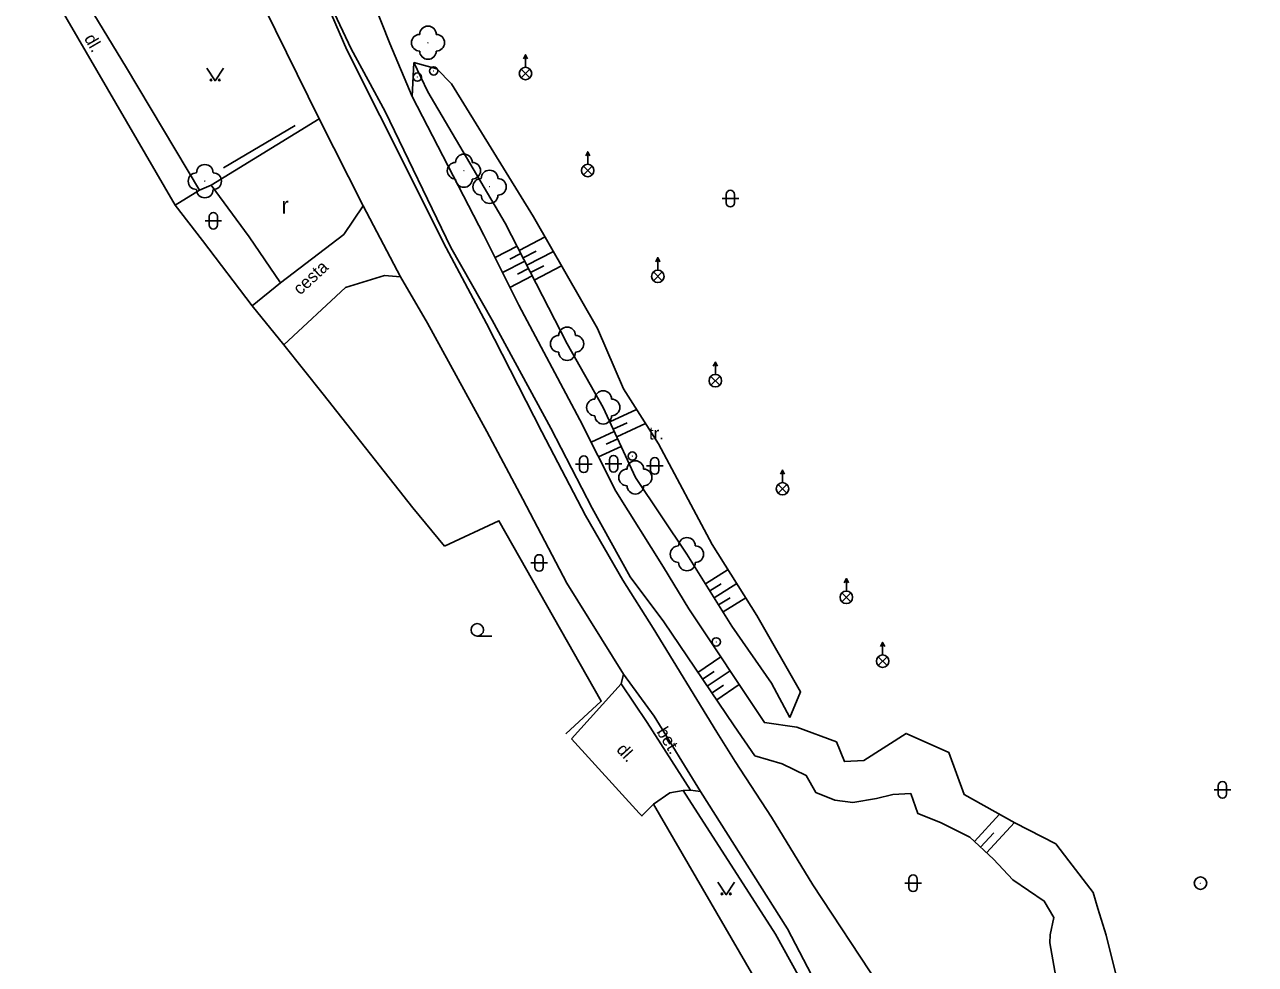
# Model space of a CAD drawing. Extents: x -582188 to -561562, y -1187250 to -1183500.
# Drawn here: x -578267.1 to -578193.2, y -1186086.2 to -1186029.8 of the extents above; entities that cross this region are included whole.
import ezdxf

# ---------------------------------------------------------------- set-up
doc = ezdxf.new("R2010")
doc.units = 0
for name, color, linetype in [('BUDOVY_MĚŘ', 7, 'Continuous'), ('MAP_ZN_BP', 7, 'Continuous'), ('POMOC_POPIS', 7, 'Continuous'), ('ROZHRANÍ_PLOCH', 7, 'Continuous'), ('VÝŠKOPIS', 7, 'Continuous'), ('ZELEŇ', 7, 'Continuous'), ('ZN_BP', 7, 'Continuous'), ('ZN_DOPLŇKOVÉ', 7, 'Continuous'), ('ZN_KULTUR', 7, 'Continuous')]:
    doc.layers.add(name, color=color, linetype=linetype)

msp = doc.modelspace()

# ---------------------------------------------------------------- linework, layer by layer
at = {"layer": 'BUDOVY_MĚŘ'}
for p, q in [((-578256.43, -1186042.75), (-578258.07, -1186040.62)), ((-578230.19, -1186077.16), (-578234.26, -1186072.68))]:
    msp.add_line(p, q, dxfattribs=at)
for points in [[(-578258.07, -1186040.62), (-578265.71, -1186027.49), (-578267.12, -1186025.25)], [(-578249.17, -1186051.97), (-578251.54, -1186049.02)]]:
    msp.add_lwpolyline(points, dxfattribs=at)
at = {"layer": 'MAP_ZN_BP'}
for radius in [0.375, 0.0005]:
    msp.add_circle((-578196.46, -1186081.36), radius, dxfattribs=at)
at = {"layer": 'ROZHRANÍ_PLOCH'}
msp.add_line((-578251.75, -1186045.28), (-578253.44, -1186046.68), dxfattribs=at)
for points in [[(-578219.75, -1186081.45), (-578222.24, -1186077.4), (-578224.42, -1186074.05), (-578225.53, -1186072.28), (-578229.35, -1186066.03), (-578231.18, -1186063.15), (-578233.42, -1186059.26), (-578236.04, -1186054.25), (-578239.37, -1186047.73), (-578241.79, -1186043.18), (-578245.77, -1186035.23), (-578247.75, -1186031.28), (-578251.05, -1186023.69), (-578253.76, -1186017.08), (-578256.85, -1186008.5), (-578257.98, -1186005.5)], [(-578234.26, -1186072.68), (-578231.28, -1186069.39), (-578231.13, -1186068.8), (-578234.53, -1186063.34), (-578237.18, -1186058.28), (-578239.34, -1186054.23), (-578242.91, -1186047.72), (-578244.54, -1186044.93), (-578246.77, -1186040.67), (-578249.42, -1186035.43), (-578252.71, -1186028.77), (-578254.42, -1186025.06), (-578254.87, -1186024.59), (-578255.45, -1186024.14), (-578257.13, -1186023.85), (-578257.51, -1186023.81), (-578258.52, -1186023.89), (-578259.53, -1186024.12), (-578260.54, -1186024.49), (-578261.18, -1186024.85), (-578263.33, -1186026.15), (-578264.37, -1186026.83), (-578261, -1186032.38)], [(-578258.07, -1186040.62), (-578256.61, -1186039.73), (-578261, -1186032.38)], [(-578251.54, -1186049.02), (-578247.83, -1186045.57), (-578245.5, -1186044.85), (-578244.54, -1186044.93)], [(-578226.5, -1186075.85), (-578229.28, -1186071.33), (-578231.13, -1186068.8)], [(-578227.11, -1186075.77), (-578229.71, -1186071.7), (-578231.28, -1186069.39)], [(-578216.48, -1186097.76), (-578216.4, -1186097.41), (-578216.48, -1186095.19), (-578217.13, -1186092.49), (-578218.12, -1186090.11), (-578219.59, -1186087.32), (-578221.27, -1186084.09), (-578226.5, -1186075.85), (-578227.11, -1186075.77), (-578227.54, -1186075.79), (-578228.35, -1186075.93), (-578229.33, -1186076.61)], [(-578225.47, -1186114.85), (-578217.9, -1186107.52), (-578215.38, -1186104.13), (-578213.87, -1186101.45), (-578213.11, -1186099.12), (-578212.78, -1186096.87), (-578213.36, -1186093.58), (-578214.32, -1186090.08), (-578215.76, -1186087.51), (-578219.75, -1186081.45)]]:
    msp.add_lwpolyline(points, dxfattribs=at)
at = {"layer": 'VÝŠKOPIS'}
for p, q in [((-578237.53, -1186043.09), (-578238.85, -1186043.77)), ((-578237.4, -1186043.34), (-578235.84, -1186042.53)), ((-578237.07, -1186043.98), (-578238.41, -1186044.66)), ((-578237.3, -1186043.53), (-578237.97, -1186043.87)), ((-578237.17, -1186043.78), (-578236.38, -1186043.38)), ((-578236.95, -1186044.23), (-578235.34, -1186043.4)), ((-578236.85, -1186044.42), (-578237.51, -1186044.77)), ((-578236.72, -1186044.67), (-578235.91, -1186044.26)), ((-578236.49, -1186045.12), (-578234.85, -1186044.27)), ((-578236.62, -1186044.87), (-578237.96, -1186045.56)), ((-578231.96, -1186053.63), (-578230.35, -1186052.89)), ((-578231.69, -1186054.22), (-578233.08, -1186054.86)), ((-578231.75, -1186054.08), (-578230.91, -1186053.7)), ((-578231.54, -1186054.54), (-578229.81, -1186053.74)), ((-578231.48, -1186054.67), (-578232.17, -1186054.99)), ((-578231.27, -1186055.13), (-578232.63, -1186055.75)), ((-578226.21, -1186063.37), (-578224.85, -1186062.52)), ((-578225.95, -1186063.79), (-578225.26, -1186063.37)), ((-578225.68, -1186064.22), (-578224.32, -1186063.36)), ((-578225.42, -1186064.64), (-578224.73, -1186064.21)), ((-578225.15, -1186065.06), (-578223.78, -1186064.21)), ((-578226.66, -1186068.69), (-578225.28, -1186067.76)), ((-578226.38, -1186069.1), (-578225.69, -1186068.64)), ((-578226.1, -1186069.52), (-578224.73, -1186068.59)), ((-578225.81, -1186069.93), (-578225.13, -1186069.47)), ((-578225.53, -1186070.35), (-578224.18, -1186069.43)), ((-578210.04, -1186078.86), (-578208.53, -1186077.22)), ((-578209.31, -1186079.54), (-578207.63, -1186077.72)), ((-578209.67, -1186079.2), (-578208.88, -1186078.33))]:
    msp.add_line(p, q, dxfattribs=at)
for points in [[(-578202.62, -1186082.87), (-578202.91, -1186081.92), (-578204.38, -1186080.01), (-578205.15, -1186079), (-578207.62, -1186077.73), (-578210.65, -1186076.03), (-578211.59, -1186073.5), (-578214.15, -1186072.36), (-578216.68, -1186073.99), (-578217.86, -1186074.05), (-578218.34, -1186072.86), (-578220.72, -1186071.98), (-578222.66, -1186071.71), (-578227.2, -1186064.87), (-578228.72, -1186062.37), (-578231.6, -1186057.81), (-578233.76, -1186053.51), (-578237.42, -1186046.63), (-578239.53, -1186042.42), (-578243.84, -1186034.09), (-578245.17, -1186030.9), (-578248.92, -1186021.45), (-578249.33, -1186019.24), (-578250.64, -1186018.18)], [(-578205.51, -1186084.95), (-578205.5, -1186084.45), (-578205.28, -1186083.41), (-578205.85, -1186082.43), (-578207.74, -1186081.15), (-578208.9, -1186079.91), (-578210.32, -1186078.6), (-578212.08, -1186077.72), (-578213.45, -1186077.18), (-578213.87, -1186075.97), (-578214.94, -1186076.02), (-578215.93, -1186076.26), (-578217.36, -1186076.51), (-578218.43, -1186076.36), (-578219.58, -1186075.9), (-578220.15, -1186074.89), (-578221.59, -1186074.18), (-578223.23, -1186073.7), (-578224.48, -1186071.9), (-578228.71, -1186065.66), (-578230.73, -1186062.96), (-578233.01, -1186058.82), (-578235.49, -1186054.01), (-578239.02, -1186047.54), (-578241.5, -1186043.17), (-578245.45, -1186035), (-578247.49, -1186031.23), (-578251.05, -1186023.69)], [(-578243.84, -1186034.09), (-578243.74, -1186032.05)], [(-578221.14, -1186071.41), (-578222.23, -1186069.34), (-578224.62, -1186065.92), (-578227.32, -1186061.59), (-578230.42, -1186056.98), (-578232.35, -1186052.77), (-578234.52, -1186048.95), (-578238.24, -1186041.71), (-578242.88, -1186033.81), (-578243.74, -1186032.05)], [(-578221.14, -1186071.41), (-578220.49, -1186069.87), (-578223.11, -1186065.27), (-578225.81, -1186061), (-578229.02, -1186054.97), (-578231.14, -1186051.65), (-578232.7, -1186048.04), (-578236.53, -1186041.32), (-578241.47, -1186033.34), (-578242.35, -1186032.44), (-578243.74, -1186032.05)], [(-578193.16, -1186096.5), (-578194.64, -1186092.79), (-578195.32, -1186091.59), (-578198.18, -1186089.13), (-578201.52, -1186086.91), (-578202.13, -1186084.47), (-578202.62, -1186082.87)], [(-578193.16, -1186096.5), (-578195.8, -1186093.08), (-578198.12, -1186091.38), (-578202.97, -1186089.67), (-578204.88, -1186088.57), (-578205.51, -1186084.95)]]:
    msp.add_lwpolyline(points, dxfattribs=at)
at = {"layer": 'ZELEŇ'}
msp.add_line((-578255.17, -1186038.38), (-578250.86, -1186035.83), dxfattribs=at)
for points in [[(-578246.77, -1186040.67), (-578247.94, -1186042.38), (-578251.75, -1186045.28), (-578253.63, -1186042.53), (-578255.91, -1186039.43), (-578249.42, -1186035.43)], [(-578255.91, -1186039.43), (-578256.61, -1186039.73)], [(-578216.9, -1186097.97), (-578216.84, -1186095.77), (-578217.61, -1186092.95), (-578218.55, -1186090.48), (-578220.12, -1186087.82), (-578221.99, -1186084.41), (-578227.54, -1186075.79)]]:
    msp.add_lwpolyline(points, dxfattribs=at)
for centre in [(-578242.88, -1186030.86), (-578240.72, -1186038.55), (-578256.29, -1186039.18), (-578239.18, -1186039.52), (-578234.52, -1186048.95), (-578232.35, -1186052.77), (-578230.42, -1186056.98), (-578227.32, -1186061.59)]:
    msp.add_circle(centre, 0.0005, dxfattribs=at)
for centre, start, end in [((-578242.88, -1186030.36), 0, 179.99999), ((-578243.38, -1186030.86), 89.99999, 269.99999), ((-578242.38, -1186030.86), 270, 89.99999), ((-578242.88, -1186031.36), 179.99999, 359.99999), ((-578241.22, -1186038.55), 89.99999, 269.99999), ((-578240.72, -1186038.05), 0, 179.99999), ((-578240.22, -1186038.55), 270, 89.99999), ((-578256.79, -1186039.18), 89.99999, 269.99999), ((-578256.29, -1186038.68), 0, 179.99999), ((-578255.79, -1186039.18), 270, 89.99999), ((-578239.18, -1186039.02), 0, 179.99999), ((-578240.72, -1186039.05), 179.99999, 359.99999), ((-578239.68, -1186039.52), 89.99999, 269.99999), ((-578238.68, -1186039.52), 270, 89.99999), ((-578256.29, -1186039.68), 179.99999, 359.99999), ((-578239.18, -1186040.02), 179.99999, 359.99999), ((-578234.52, -1186048.45), 0, 179.99999), ((-578235.02, -1186048.95), 89.99999, 269.99999), ((-578234.02, -1186048.95), 270, 89.99999), ((-578234.52, -1186049.45), 179.99999, 359.99999), ((-578232.35, -1186052.27), 0, 179.99999), ((-578232.85, -1186052.77), 89.99999, 269.99999), ((-578231.85, -1186052.77), 270, 89.99999), ((-578232.35, -1186053.27), 179.99999, 359.99999), ((-578230.92, -1186056.98), 89.99999, 269.99999), ((-578230.42, -1186056.48), 0, 179.99999), ((-578229.92, -1186056.98), 270, 89.99999), ((-578230.42, -1186057.48), 179.99999, 359.99999), ((-578227.32, -1186061.09), 0, 179.99999), ((-578227.82, -1186061.59), 89.99999, 269.99999), ((-578226.82, -1186061.59), 270, 89.99999), ((-578227.32, -1186062.09), 179.99999, 359.99999)]:
    msp.add_arc(centre, 0.5, start, end, dxfattribs=at)
at = {"layer": 'ZN_BP'}
for p, q in [((-578237.02, -1186032.335), (-578237.02, -1186031.585)), ((-578237.285, -1186032.974), (-578236.756, -1186032.446)), ((-578236.756, -1186032.978), (-578237.285, -1186032.446)), ((-578233.28, -1186038.165), (-578233.28, -1186037.415)), ((-578233.545, -1186038.804), (-578233.016, -1186038.276)), ((-578233.016, -1186038.808), (-578233.545, -1186038.276)), ((-578229.07, -1186044.525), (-578229.07, -1186043.775)), ((-578229.335, -1186045.164), (-578228.806, -1186044.636)), ((-578228.806, -1186045.168), (-578229.335, -1186044.636)), ((-578225.61, -1186050.795), (-578225.61, -1186050.045)), ((-578225.875, -1186051.434), (-578225.346, -1186050.906)), ((-578225.346, -1186051.438), (-578225.875, -1186050.906)), ((-578221.58, -1186057.285), (-578221.58, -1186056.535)), ((-578221.845, -1186057.924), (-578221.316, -1186057.396)), ((-578221.316, -1186057.928), (-578221.845, -1186057.396)), ((-578217.74, -1186063.805), (-578217.74, -1186063.055)), ((-578218.005, -1186064.444), (-578217.476, -1186063.916)), ((-578217.476, -1186064.448), (-578218.005, -1186063.916)), ((-578215.56, -1186067.645), (-578215.56, -1186066.895)), ((-578215.825, -1186068.284), (-578215.296, -1186067.756)), ((-578215.296, -1186068.288), (-578215.825, -1186067.756))]:
    msp.add_line(p, q, dxfattribs=at)
for points in [[(-578237.145, -1186031.835), (-578237.02, -1186031.585), (-578236.895, -1186031.835)], [(-578233.405, -1186037.665), (-578233.28, -1186037.415), (-578233.155, -1186037.665)], [(-578229.195, -1186044.025), (-578229.07, -1186043.775), (-578228.945, -1186044.025)], [(-578225.735, -1186050.295), (-578225.61, -1186050.045), (-578225.485, -1186050.295)], [(-578221.705, -1186056.785), (-578221.58, -1186056.535), (-578221.455, -1186056.785)], [(-578217.865, -1186063.305), (-578217.74, -1186063.055), (-578217.615, -1186063.305)], [(-578215.685, -1186067.145), (-578215.56, -1186066.895), (-578215.435, -1186067.145)]]:
    msp.add_lwpolyline(points, dxfattribs=at)
for centre, radius in [((-578243.52, -1186032.93), 0.25), ((-578242.54, -1186032.56), 0.25), ((-578242.54, -1186032.56), 0.0005), ((-578237.02, -1186032.71), 0.375), ((-578243.52, -1186032.93), 0.0005), ((-578233.28, -1186038.54), 0.375), ((-578229.07, -1186044.9), 0.375), ((-578225.61, -1186051.17), 0.375), ((-578221.58, -1186057.66), 0.375), ((-578217.74, -1186064.18), 0.375), ((-578225.56, -1186066.86), 0.25), ((-578225.56, -1186066.86), 0.0005), ((-578215.56, -1186068.02), 0.375)]:
    msp.add_circle(centre, radius, dxfattribs=at)
at = {"layer": 'ZN_DOPLŇKOVÉ'}
for p, q in [((-578253.44, -1186046.68), (-578256.43, -1186042.75)), ((-578251.54, -1186049.02), (-578253.44, -1186046.68))]:
    msp.add_line(p, q, dxfattribs=at)
for points in [[(-578243.79, -1186058.81), (-578249.17, -1186051.97)], [(-578241.89, -1186061.11), (-578243.79, -1186058.81)], [(-578234.6, -1186072.38), (-578232.47, -1186070.43), (-578238.62, -1186059.58), (-578241.89, -1186061.11)], [(-578216.9, -1186097.97), (-578229.33, -1186076.61), (-578230.02, -1186077.32), (-578230.19, -1186077.16)]]:
    msp.add_lwpolyline(points, dxfattribs=at)
for radius in [0.25, 0.0005]:
    msp.add_circle((-578230.601, -1186055.7), radius, dxfattribs=at)
at = {"layer": 'ZN_KULTUR'}
for p, q in [((-578225.21, -1186040.23), (-578224.21, -1186040.23)), ((-578224.96, -1186040.48), (-578224.96, -1186039.98)), ((-578224.46, -1186040.48), (-578224.46, -1186039.98)), ((-578256.28, -1186041.56), (-578255.28, -1186041.56)), ((-578256.03, -1186041.81), (-578256.03, -1186041.31)), ((-578255.53, -1186041.81), (-578255.53, -1186041.31)), ((-578234.02, -1186056.19), (-578233.02, -1186056.19)), ((-578233.77, -1186056.44), (-578233.77, -1186055.94)), ((-578233.27, -1186056.44), (-578233.27, -1186055.94)), ((-578232.23, -1186056.16), (-578231.23, -1186056.16)), ((-578231.98, -1186056.41), (-578231.98, -1186055.91)), ((-578231.48, -1186056.41), (-578231.48, -1186055.91)), ((-578229.75, -1186056.29), (-578228.75, -1186056.29)), ((-578229.5, -1186056.54), (-578229.5, -1186056.04)), ((-578229, -1186056.54), (-578229, -1186056.04)), ((-578236.7, -1186062.12), (-578235.7, -1186062.12)), ((-578236.45, -1186062.37), (-578236.45, -1186061.87)), ((-578235.95, -1186062.37), (-578235.95, -1186061.87)), ((-578239.92, -1186066.515), (-578239.045, -1186066.515)), ((-578195.64, -1186075.75), (-578194.64, -1186075.75)), ((-578195.39, -1186076), (-578195.39, -1186075.5)), ((-578194.89, -1186076), (-578194.89, -1186075.5)), ((-578214.23, -1186081.36), (-578213.23, -1186081.36)), ((-578213.98, -1186081.61), (-578213.98, -1186081.11)), ((-578213.48, -1186081.61), (-578213.48, -1186081.11))]:
    msp.add_line(p, q, dxfattribs=at)
for points in [[(-578256.17, -1186032.4), (-578255.67, -1186033.15), (-578255.17, -1186032.4)], [(-578225.46, -1186081.3), (-578224.96, -1186082.05), (-578224.46, -1186081.3)]]:
    msp.add_lwpolyline(points, dxfattribs=at)
for centre, radius in [((-578255.92, -1186033.1), 0.05), ((-578255.42, -1186033.1), 0.05), ((-578239.92, -1186066.14), 0.375), ((-578225.21, -1186082), 0.05), ((-578224.71, -1186082), 0.05)]:
    msp.add_circle(centre, radius, dxfattribs=at)
for centre, start, end in [((-578224.71, -1186039.98), 0, 179.99999), ((-578224.71, -1186040.48), 179.99999, 359.99999), ((-578255.78, -1186041.31), 0, 179.99999), ((-578255.78, -1186041.81), 179.99999, 359.99999), ((-578233.52, -1186055.94), 0, 179.99999), ((-578231.73, -1186055.91), 0, 179.99999), ((-578229.25, -1186056.04), 0, 179.99999), ((-578233.52, -1186056.44), 179.99999, 359.99999), ((-578231.73, -1186056.41), 179.99999, 359.99999), ((-578229.25, -1186056.54), 179.99999, 359.99999), ((-578236.2, -1186061.87), 0, 179.99999), ((-578236.2, -1186062.37), 179.99999, 359.99999), ((-578195.14, -1186075.5), 0, 179.99999), ((-578195.14, -1186076), 179.99999, 359.99999), ((-578213.73, -1186081.11), 0, 179.99999), ((-578213.73, -1186081.61), 179.99999, 359.99999)]:
    msp.add_arc(centre, 0.25, start, end, dxfattribs=at)

# ---------------------------------------------------------------- texts
at = {"layer": 'POMOC_POPIS'}
for s, rotation, p in [('dl.', 300.19399, (-578263.57, -1186030.6)), ('cesta', 42.92034, (-578250.56, -1186046.06)), ('bet.', 301.59336, (-578229.17, -1186072.26)), ('dl.', 312.25459, (-578231.6, -1186073.37))]:
    msp.add_text(s, height=0.75, rotation=rotation, dxfattribs=at).set_placement(p)
msp.add_text('tr.', height=0.75, dxfattribs=at).set_placement((-578229.6, -1186054.7))
at = {"layer": 'ZN_KULTUR'}
msp.add_text('r', height=1, dxfattribs=at).set_placement((-578251.688, -1186041.132))

doc.saveas('drawing.dxf')
